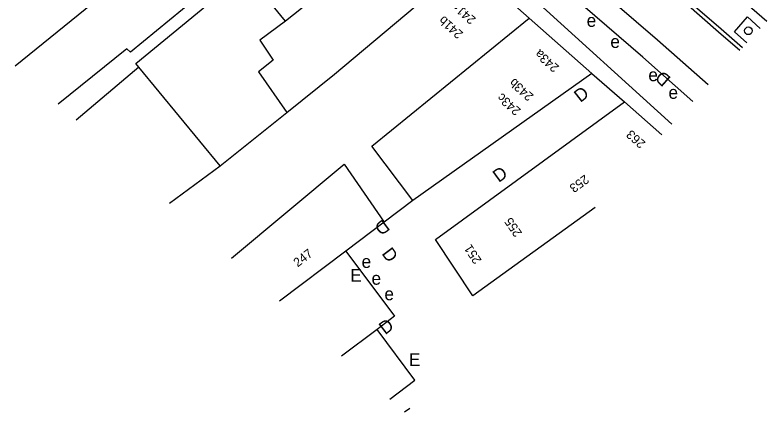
# Model space of a CAD drawing. Extents: x 81617 to 82144, y 454649 to 455150.
# Drawn here: x 81700.2 to 81758.8, y 454649 to 454680 of the extents above; entities that cross this region are included whole.
import ezdxf

# ---------------------------------------------------------------- set-up
doc = ezdxf.new("R2010")
doc.units = 0
doc.layers.add('B-WE-OG-TOPOGRAFIE-G', color=7, linetype='Continuous')
doc.layers.add('B-WE-VW-MARKERING-G', color=7, linetype='Continuous')

msp = doc.modelspace()

# ---------------------------------------------------------------- linework, layer by layer
at = {"layer": 'B-WE-OG-TOPOGRAFIE-G'}
for p, q in [((81700.206, 454676.039), (81723.254, 454694.862)), ((81742.024, 454694.015), (81758.788, 454679.535)), ((81736.067, 454685.401), (81751.371, 454671.486)), ((81709.857, 454675.928), (81704.969, 454671.799)), ((81745.134, 454675.451), (81747.676, 454673.23)), ((81716.192, 454668.239), (81721.377, 454672.411)), ((81728.412, 454655.471), (81725.652, 454653.385))]:
    msp.add_line(p, q, dxfattribs=at)
for points in [[(81727.987, 454702.211), (81739.09, 454692.554), (81752.463, 454680.921), (81755.021, 454678.695)], [(81729.3, 454701.466), (81739.287, 454692.78), (81752.66, 454681.147), (81755.218, 454678.921)], [(81753.001, 454673.256), (81749.115, 454676.722), (81735.271, 454688.668), (81725.797, 454697.026), (81722.581, 454699.735)], [(81726.796, 454691.541), (81716.827, 454683.516), (81714.706, 454686.208), (81712.975, 454684.809), (81715.281, 454682.136), (81709.19, 454677.095), (81708.906, 454677.365), (81703.572, 454673.043)], [(81712.245, 454665.322), (81716.192, 454668.239), (81709.857, 454675.928), (81709.624, 454676.21), (81718.047, 454683.199), (81720.875, 454685.478), (81727.664, 454690.931)], [(81727.664, 454690.931), (81731.283, 454687.723), (81735.406, 454684.071), (81740.258, 454679.771), (81745.134, 454675.451), (81731.189, 454665.536), (81728.959, 454663.85), (81725.968, 454661.587)], [(81721.377, 454672.411), (81725.093, 454675.401), (81735.406, 454684.071)], [(81719.728, 454681.448), (81722.335, 454683.558), (81723.893, 454681.633), (81721.286, 454679.522), (81719.728, 454681.448)], [(81731.189, 454665.536), (81727.996, 454669.785), (81740.258, 454679.771)], [(81756.26, 454678.682), (81757.282, 454679.852), (81758.261, 454678.964)], [(81721.286, 454679.522), (81719.271, 454678.029), (81720.305, 454676.483), (81719.167, 454675.563), (81721.377, 454672.411)], [(81755.021, 454678.695), (81756.682, 454677.25)], [(81755.218, 454678.921), (81756.885, 454677.471)], [(81757.23, 454677.844), (81756.26, 454678.682)], [(81745.394, 454665), (81735.873, 454658.095), (81732.953, 454662.485), (81747.676, 454673.23), (81750.6, 454670.65)], [(81717.063, 454661.032), (81725.861, 454668.374), (81728.959, 454663.85)], [(81725.968, 454661.587), (81720.817, 454657.69)], [(81725.968, 454661.587), (81729.761, 454656.517), (81728.412, 454655.471)], [(81729.413, 454650.037), (81731.361, 454651.513), (81728.412, 454655.471)], [(81730.537, 454649.036), (81730.959, 454649.336)]]:
    msp.add_lwpolyline(points, dxfattribs=at)
msp.add_circle((81757.345, 454678.771), 0.3, dxfattribs=at)
at = {"layer": 'B-WE-VW-MARKERING-G'}
msp.add_lwpolyline([(81754.205, 454674.562), (81750.269, 454678.038), (81736.422, 454689.987), (81726.94, 454698.352), (81714.491, 454708.275)], dxfattribs=at)

# ---------------------------------------------------------------- texts
at = {"layer": 'B-WE-OG-TOPOGRAFIE-G'}
for s, height, rotation, p in [('241a', 0.7, 138.45615, (81736.159, 454679.73)), ('241b', 0.7, 138.45615, (81735.164, 454678.607)), ('243a', 0.7, 138.45615, (81742.644, 454675.988)), ('243b', 0.7, 138.45615, (81740.655, 454673.743)), ('D', 1, 138.62847, (81751.361, 454675.089)), ('243c', 0.7, 138.45615, (81739.661, 454672.619)), ('D', 1, 38.16583, (81744.252, 454673.138)), ('263', 0.7, 138.58282, (81749.385, 454670.056)), ('D', 1, 36.12586, (81737.891, 454666.899)), ('253', 0.7, 216.12236, (81744.598, 454667.579)), ('D', 1, 217.09882, (81728.895, 454664.12)), ('255', 0.7, 124.27955, (81739.743, 454662.993)), ('251', 0.7, 123.48046, (81736.584, 454660.879)), ('247', 0.7, 37.33695, (81722.225, 454660.308)), ('D', 1, 306.79946, (81728.732, 454661.387)), ('D', 1, 37.78871, (81729.045, 454655.024))]:
    msp.add_text(s, height=height, rotation=rotation, dxfattribs=at).set_placement(p)
for s, p in [('e', (81744.743, 454679.08)), ('e', (81746.588, 454677.435)), ('e', (81749.549, 454674.839)), ('e', (81751.115, 454673.468)), ('e', (81727.207, 454660.273)), ('E', (81726.321, 454659.201)), ('e', (81727.981, 454658.964)), ('e', (81728.984, 454657.751)), ('E', (81730.895, 454652.619))]:
    msp.add_text(s, height=1, dxfattribs=at).set_placement(p)

doc.saveas('drawing.dxf')
